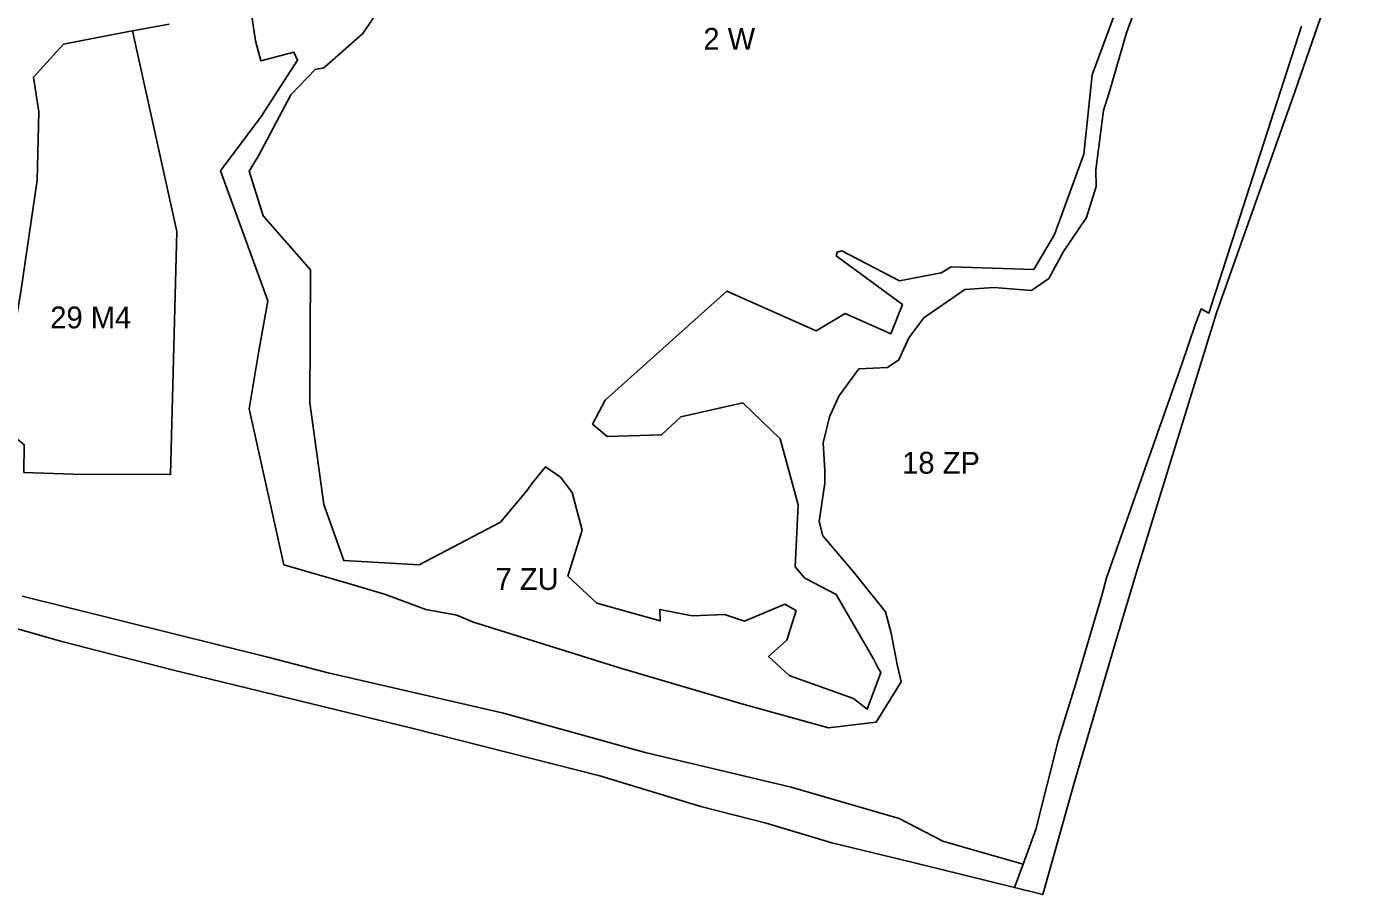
# Model space of a CAD drawing. Extents: x 7437831 to 7440315, y 5545798 to 5547888.
# Drawn here: x 7439385 to 7439992, y 5545798 to 5546197 of the extents above; entities that cross this region are included whole.
import ezdxf

# ---------------------------------------------------------------- set-up
doc = ezdxf.new("R2010")
doc.units = 0
doc.layers.add('linie_rozgraniczajace', color=7, linetype='Continuous')
doc.layers.add('oznaczenia_przeznaczen', color=7, linetype='Continuous')

msp = doc.modelspace()

# ---------------------------------------------------------------- linework, layer by layer
at = {"layer": 'linie_rozgraniczajace'}
for points in [[(7439909.44, 5546247.36), (7439890.04, 5546194.08), (7439882.27, 5546167.07), (7439879.51, 5546158.35), (7439875.97, 5546131.11), (7439876.09, 5546123.37), (7439871.59, 5546109.25), (7439861.09, 5546093.62), (7439854.36, 5546081.24), (7439846.43, 5546075.71), (7439829.13, 5546077.06), (7439815.77, 5546076.08), (7439796.92, 5546063.19), (7439790.01, 5546053.98), (7439785.47, 5546043.89), (7439780.31, 5546040.36), (7439767.2, 5546039.7), (7439757.98, 5546027.09), (7439753.65, 5546017.73), (7439750.7, 5546005.66), (7439751.59, 5545993.08), (7439751.47, 5545987.16), (7439748.86, 5545969.57), (7439750.67, 5545963.04), (7439764.59, 5545946.59), (7439779.44, 5545928.11), (7439782.05, 5545918.39), (7439784.77, 5545903.9), (7439786.49, 5545896.02), (7439775.08, 5545877.42), (7439753.17, 5545874.89), (7439713.44, 5545885.87), (7439657.2, 5545902.42), (7439590.32, 5545923.41), (7439582.65, 5545926.58), (7439568.35, 5545929.22), (7439549.9, 5545936.14), (7439533.91, 5545940.8), (7439503.22, 5545949.72), (7439487.24, 5546021.27), (7439491.58, 5546047), (7439495.84, 5546070.96), (7439474.15, 5546130.66), (7439492.83, 5546155.65), (7439509.53, 5546181.46), (7439507.85, 5546185.14), (7439492.61, 5546181.09), (7439490.15, 5546190.37), (7439487.44, 5546208.89)], [(7439487.44, 5546208.89), (7439490.15, 5546190.37), (7439492.61, 5546181.09), (7439507.85, 5546185.14), (7439509.53, 5546181.46), (7439492.83, 5546155.65), (7439474.15, 5546130.66), (7439495.84, 5546070.96), (7439491.58, 5546047), (7439487.24, 5546021.27), (7439503.22, 5545949.72), (7439533.91, 5545940.8), (7439549.9, 5545936.14), (7439568.35, 5545929.22), (7439582.65, 5545926.58), (7439590.32, 5545923.41), (7439657.2, 5545902.42), (7439713.44, 5545885.87), (7439753.17, 5545874.89), (7439775.08, 5545877.42), (7439786.49, 5545896.02), (7439784.77, 5545903.9), (7439782.05, 5545918.39), (7439779.44, 5545928.11), (7439764.59, 5545946.59), (7439750.67, 5545963.04), (7439748.86, 5545969.57), (7439751.47, 5545987.16), (7439751.59, 5545993.08), (7439750.7, 5546005.66), (7439753.65, 5546017.73), (7439757.98, 5546027.09), (7439767.2, 5546039.7), (7439780.31, 5546040.36), (7439785.47, 5546043.89), (7439790.01, 5546053.98), (7439796.92, 5546063.19), (7439815.77, 5546076.08), (7439829.13, 5546077.06), (7439846.43, 5546075.71), (7439854.36, 5546081.24), (7439861.09, 5546093.62), (7439871.59, 5546109.25), (7439876.09, 5546123.37), (7439875.97, 5546131.11), (7439879.51, 5546158.35), (7439882.27, 5546167.07), (7439890.04, 5546194.08), (7439909.44, 5546247.36)], [(7439572.52, 5546242.78), (7439539.47, 5546193.7), (7439521.48, 5546177.93), (7439517.55, 5546177.18), (7439506.39, 5546165.59), (7439491.58, 5546137.45), (7439487.34, 5546130.53), (7439493.78, 5546109.92), (7439515.46, 5546085.2), (7439515.1, 5546024.06), (7439521.62, 5545977.48), (7439530.71, 5545951.67), (7439565.24, 5545949.67), (7439602.63, 5545969.34), (7439615.23, 5545984.37), (7439617.25, 5545987.28), (7439623.34, 5545994.78), (7439630.2, 5545989.93), (7439635.52, 5545982.91), (7439640.13, 5545965.62), (7439633.59, 5545944.49), (7439646.91, 5545932.14), (7439675.99, 5545923.98), (7439675.86, 5545929.26), (7439690.69, 5545926.28), (7439705.42, 5545926.96), (7439714.71, 5545923.82), (7439733.17, 5545931.64), (7439738.41, 5545928.68), (7439734.16, 5545915.1), (7439725.68, 5545907.68), (7439735.14, 5545898.96), (7439764.71, 5545888.39), (7439771.03, 5545883.39), (7439777.21, 5545900.31), (7439775.85, 5545902.5), (7439773.99, 5545906.23), (7439756.76, 5545936.11), (7439742.38, 5545943.54), (7439737.98, 5545948.74), (7439739.27, 5545977.22), (7439731.05, 5546007.53), (7439713.9, 5546024.13), (7439685.5, 5546017.7), (7439676.58, 5546009.37), (7439651.65, 5546008.6), (7439644.94, 5546014.26), (7439650.67, 5546025.3), (7439706.5, 5546075.38), (7439747.55, 5546057.13), (7439760.91, 5546065.11), (7439781.77, 5546055.71), (7439787.15, 5546069.26), (7439756.74, 5546091.6), (7439757.17, 5546093.24), (7439759.33, 5546093.9), (7439785.74, 5546080.18), (7439804.89, 5546083.83), (7439809.58, 5546086.54), (7439847.5, 5546085.4), (7439856.88, 5546101.45), (7439870.42, 5546138.25), (7439874.23, 5546174.75), (7439898.74, 5546241.04)], [(7439898.74, 5546241.04), (7439874.23, 5546174.75), (7439870.42, 5546138.25), (7439856.88, 5546101.45), (7439847.5, 5546085.4), (7439809.58, 5546086.54), (7439804.89, 5546083.83), (7439785.74, 5546080.18), (7439759.33, 5546093.9), (7439757.17, 5546093.24), (7439756.74, 5546091.6), (7439787.15, 5546069.26), (7439781.77, 5546055.71), (7439760.91, 5546065.11), (7439747.55, 5546057.13), (7439706.5, 5546075.38), (7439650.67, 5546025.3), (7439644.94, 5546014.26), (7439651.65, 5546008.6), (7439676.58, 5546009.37), (7439685.5, 5546017.7), (7439713.9, 5546024.13), (7439731.05, 5546007.53), (7439739.27, 5545977.22), (7439737.98, 5545948.74), (7439742.38, 5545943.54), (7439756.76, 5545936.11), (7439773.99, 5545906.23), (7439775.85, 5545902.5), (7439777.21, 5545900.31), (7439771.03, 5545883.39), (7439764.71, 5545888.39), (7439735.14, 5545898.96), (7439725.68, 5545907.68), (7439734.16, 5545915.1), (7439738.41, 5545928.68), (7439733.17, 5545931.64), (7439714.71, 5545923.82), (7439705.42, 5545926.96), (7439690.69, 5545926.28), (7439675.86, 5545929.26), (7439675.99, 5545923.98), (7439646.91, 5545932.14), (7439633.59, 5545944.49), (7439640.13, 5545965.62), (7439635.52, 5545982.91), (7439630.2, 5545989.93), (7439623.34, 5545994.78), (7439617.25, 5545987.28), (7439615.23, 5545984.37), (7439602.63, 5545969.34), (7439565.24, 5545949.67), (7439530.71, 5545951.67), (7439521.62, 5545977.48), (7439515.1, 5546024.06), (7439515.46, 5546085.2), (7439493.78, 5546109.92), (7439487.34, 5546130.53), (7439491.58, 5546137.45), (7439506.39, 5546165.59), (7439517.55, 5546177.18), (7439521.48, 5546177.93), (7439539.47, 5546193.7), (7439572.52, 5546242.78)], [(7439992.38, 5546239.53), (7439967.33, 5546166.94), (7439931.32, 5546065.37), (7439895.19, 5545948.34), (7439886.27, 5545918.74), (7439866.1, 5545850.01), (7439851.58, 5545798.3), (7439838.64, 5545801.5), (7439842.57, 5545812.3), (7439848.36, 5545828.2), (7439858.8, 5545869.56), (7439867.16, 5545896.72), (7439878.73, 5545935.62), (7439880.82, 5545943.7), (7439915.36, 5546041.88), (7439921.54, 5546059.97), (7439924.27, 5546067.21), (7439927.82, 5546065.29), (7439970.26, 5546197.06)], [(7439450.62, 5546198.06), (7439433.75, 5546194.86), (7439422.48, 5546192.72), (7439402.13, 5546188.86), (7439388.24, 5546173.71), (7439390.8, 5546157.73), (7439389.99, 5546126.42), (7439382.67, 5546076.21)], [(7439970.26, 5546197.06), (7439927.82, 5546065.29), (7439924.27, 5546067.21), (7439921.54, 5546059.97), (7439915.36, 5546041.88), (7439880.82, 5545943.7), (7439878.73, 5545935.62), (7439867.16, 5545896.72), (7439858.8, 5545869.56), (7439848.36, 5545828.2), (7439842.57, 5545812.3), (7439825.91, 5545816.94), (7439805.62, 5545822.82), (7439785.63, 5545833.21), (7439736.02, 5545847.59), (7439669.06, 5545863.51), (7439603.98, 5545881.55), (7439523.47, 5545900.17), (7439495.91, 5545907.34), (7439383.16, 5545935.37)], [(7439383.92, 5545992.14), (7439406.69, 5545991.33), (7439451.23, 5545991.15), (7439454.14, 5546102.8), (7439433.75, 5546194.86), (7439450.62, 5546198.06)], [(7439383.16, 5545935.37), (7439495.91, 5545907.34), (7439523.47, 5545900.17), (7439603.98, 5545881.55), (7439669.06, 5545863.51), (7439736.02, 5545847.59), (7439785.63, 5545833.21), (7439805.62, 5545822.82), (7439825.91, 5545816.94), (7439842.57, 5545812.3), (7439838.64, 5545801.5), (7439792.13, 5545813), (7439754.81, 5545822.04), (7439724.66, 5545831.08), (7439694.61, 5545838.76), (7439648.3, 5545852.86), (7439561.99, 5545874.75), (7439452, 5545901.53), (7439401.35, 5545914.55), (7439377.07, 5545921.34)]]:
    msp.add_lwpolyline(points, dxfattribs=at)
msp.add_lwpolyline([(7439433.75, 5546194.86), (7439454.14, 5546102.8), (7439451.23, 5545991.15), (7439406.69, 5545991.33), (7439383.92, 5545992.14), (7439384.02, 5546004.85), (7439379.16, 5546008.91), (7439377.24, 5546043.59), (7439382.67, 5546076.21), (7439389.99, 5546126.42), (7439390.8, 5546157.73), (7439388.24, 5546173.71), (7439402.13, 5546188.86), (7439422.48, 5546192.72)], close=True, dxfattribs=at)

# ---------------------------------------------------------------- texts
at = {"layer": 'oznaczenia_przeznaczen'}
for s, p in [('2 W', (7439695.7743, 5546186.25)), ('29 M4', (7439395.9805, 5546058.31)), ('18 ZP', (7439787.0183, 5545991.58)), ('7 ZU', (7439600.3853, 5545938.2))]:
    msp.add_text(s, height=10, dxfattribs=at).set_placement(p)

doc.saveas('drawing.dxf')
